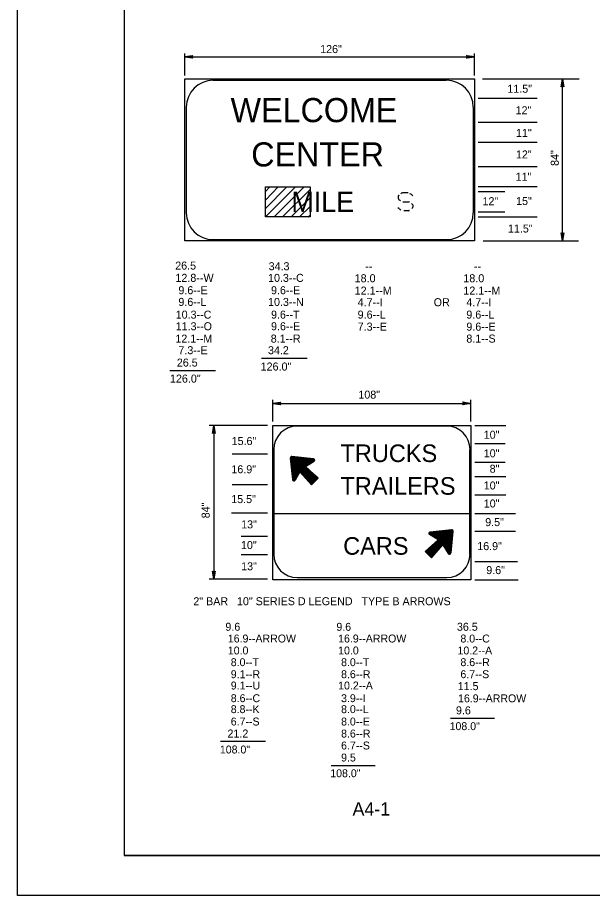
# Model space of a CAD drawing. Extents: x 2189973 to 2192941, y 2147557 to 2151454.
# Drawn here: x 2189973 to 2190680, y 2147557 to 2148636 of the extents above; entities that cross this region are included whole.
import ezdxf

# ---------------------------------------------------------------- set-up
doc = ezdxf.new("R2010")
doc.units = 0
doc.layers.add('Default', color=7, linetype='Continuous')
doc.layers.add('PLT-BNDY', color=7, linetype='Continuous')

# ---------------------------------------------------------------- blocks, each defined once
blk = doc.blocks.new('RARROW')
at = {"layer": 'Default'}
blk.add_lwpolyline([(-18.156, 2.28), (-17.479, 0.966), (0, 0), (-18.156, 2.28), (-19.086, 3.077), (0, 0), (-17.465, -0.864), (-18.103, -2.164), (0, 0), (-19.086, -3.033), (-18.103, -2.164)], dxfattribs=at)

msp = doc.modelspace()

# ---------------------------------------------------------------- linework, layer by layer
at = {"layer": 'Default'}
for p, q in [((2190104.5, 2149456.4), (2190104.5, 2147606)), ((2190179.1, 2148565.2), (2190179.1, 2148592.3)), ((2190535.5, 2148565.2), (2190535.5, 2148592.3)), ((2190179.1, 2148588.2), (2190535.5, 2148588.2)), ((2190179.1, 2148561.1), (2190535.5, 2148561.1)), ((2190179.1, 2148361.8), (2190179.1, 2148561.1)), ((2190500.6, 2148559.1), (2190213.6, 2148559.1)), ((2190535.5, 2148561.1), (2190535.5, 2148361.8)), ((2190545.3, 2148561.1), (2190664, 2148561.1)), ((2190643.6, 2148361.8), (2190643.6, 2148561.1)), ((2190540, 2148537.3), (2190612.5, 2148537.3)), ((2190180.8, 2148525.9), (2190180.8, 2148396.7)), ((2190533.9, 2148396.7), (2190533.9, 2148525.9)), ((2190540, 2148507.8), (2190612.5, 2148507.8)), ((2190540, 2148483.2), (2190612.5, 2148483.2)), ((2190540, 2148453.3), (2190612.5, 2148453.3)), ((2190540, 2148428.7), (2190612.5, 2148428.7)), ((2190540, 2148422.5), (2190572.8, 2148422.5)), ((2190540, 2148397.5), (2190572.8, 2148397.5)), ((2190540, 2148391.3), (2190612.5, 2148391.3)), ((2190213.6, 2148363.5), (2190500.6, 2148363.5)), ((2190535.5, 2148361.8), (2190179.1, 2148361.8)), ((2190545.8, 2148361.8), (2190663.1, 2148361.8)), ((2190273.2, 2148217.5), (2190329.3, 2148217.5)), ((2190160.6, 2148202.3), (2190216.9, 2148202.3)), ((2190287.2, 2148139.8), (2190287.2, 2148166.5)), ((2190287.2, 2148162), (2190530.8, 2148162)), ((2190530.8, 2148139.8), (2190530.8, 2148166.5)), ((2190280.7, 2148134.9), (2190208.9, 2148134.9)), ((2190214.7, 2148134.9), (2190214.7, 2147945.8)), ((2190287.2, 2148109.1), (2190287.2, 2148127.1)), ((2190535.8, 2148134.9), (2190573.8, 2148134.9)), ((2190288.5, 2148105), (2190288.5, 2147976.2)), ((2190529.6, 2147976.2), (2190529.6, 2148105)), ((2190535.8, 2148112.8), (2190573.2, 2148112.8)), ((2190280.7, 2148099.6), (2190237.4, 2148099.6)), ((2190308.6, 2148094.7), (2190311.4, 2148068.5)), ((2190309, 2148095.9), (2190309, 2148095.9)), ((2190309, 2148095.9), (2190309, 2148095.9)), ((2190337.3, 2148093.9), (2190310.6, 2148096.8)), ((2190310.6, 2148095.1), (2190310.6, 2148095.1)), ((2190336.5, 2148092.3), (2190336.5, 2148092.3)), ((2190339.3, 2148092.3), (2190339.3, 2148092.3)), ((2190339.3, 2148092.3), (2190339.3, 2148092.3)), ((2190327.4, 2148084.5), (2190338.1, 2148091)), ((2190327.4, 2148084.5), (2190327.4, 2148084.5)), ((2190343, 2148070.1), (2190327.4, 2148084.5)), ((2190535.8, 2148089.8), (2190573.2, 2148089.8)), ((2190320.5, 2148077.9), (2190314.7, 2148067.6)), ((2190320.5, 2148077.9), (2190320.5, 2148077.9)), ((2190320.5, 2148077.9), (2190334.8, 2148061.9)), ((2190324.1, 2148081.2), (2190324.1, 2148081.2)), ((2190535.8, 2148072.2), (2190573.8, 2148072.2)), ((2190280.7, 2148061.9), (2190237.4, 2148061.9)), ((2190313.5, 2148068.5), (2190313.5, 2148068.5)), ((2190313.5, 2148066), (2190313.5, 2148066)), ((2190313.5, 2148066), (2190313.5, 2148066)), ((2190334.8, 2148061.9), (2190343, 2148070.1)), ((2190334.8, 2148061.9), (2190334.8, 2148061.9)), ((2190343, 2148070.1), (2190343, 2148070.1)), ((2190535.8, 2148049.6), (2190573.8, 2148049.6)), ((2190287.2, 2148022.1), (2190287.2, 2148034)), ((2190280.7, 2148027), (2190236.6, 2148027)), ((2190287.2, 2148026.6), (2190529.6, 2148026.6)), ((2190535.8, 2148026.6), (2190585.9, 2148026.6)), ((2190507.1, 2148006.5), (2190480.8, 2148003.7)), ((2190280.7, 2147998.3), (2190248.3, 2147998.3)), ((2190478.8, 2148001.6), (2190478.8, 2148001.6)), ((2190478.8, 2148001.6), (2190478.8, 2148001.6)), ((2190490.7, 2147994.2), (2190480, 2148000.8)), ((2190480.8, 2148001.6), (2190480.8, 2148001.6)), ((2190506.6, 2147978.2), (2190509.1, 2148004.5)), ((2190507.1, 2148004.5), (2190507.1, 2148004.5)), ((2190535.8, 2148004.9), (2190585.9, 2148004.9)), ((2190490.7, 2147994.2), (2190474.7, 2147979.9)), ((2190482.5, 2147972.1), (2190496.4, 2147988.1)), ((2190490.7, 2147994.2), (2190490.7, 2147994.2)), ((2190493.5, 2147991), (2190493.5, 2147991)), ((2190496.4, 2147988.1), (2190496.4, 2147988.1)), ((2190496.4, 2147988.1), (2190503, 2147977.4)), ((2190280.7, 2147975.8), (2190248.3, 2147975.8)), ((2190474.7, 2147979.9), (2190474.7, 2147979.9)), ((2190474.7, 2147979.9), (2190482.5, 2147972.1)), ((2190504.6, 2147978.7), (2190504.6, 2147978.7)), ((2190504.6, 2147976.2), (2190504.6, 2147976.2)), ((2190504.6, 2147976.2), (2190504.6, 2147976.2)), ((2190482.5, 2147972.1), (2190482.5, 2147972.1)), ((2190535.8, 2147967.6), (2190588.2, 2147967.6)), ((2190280.7, 2147945.8), (2190208.9, 2147945.8)), ((2190535.8, 2147945), (2190589, 2147945)), ((2190505.8, 2147774.8), (2190559.8, 2147774.8)), ((2190223, 2147746.5), (2190278.3, 2147746.5)), ((2190358.9, 2147716.6), (2190413.3, 2147716.6)), ((2192683.2, 2147606), (2190104.5, 2147606)), ((2190104.5, 2147606), (2192027, 2147606))]:
    msp.add_line(p, q, dxfattribs=at)
msp.add_lwpolyline([(2190278.4, 2148391.3), (2190278.4, 2148428.3), (2190333.3, 2148428.3), (2190333.3, 2148391.3)], close=True, dxfattribs=at)
for points in [[(2190278.4, 2148391.3), (2190315.3, 2148428.3)], [(2190278.4, 2148401.6), (2190304.6, 2148428.3)], [(2190278.4, 2148411.8), (2190293.9, 2148428.3)], [(2190278.4, 2148422.5), (2190283.7, 2148428.3)], [(2190289, 2148391.3), (2190325.9, 2148428.3)], [(2190299.3, 2148391.3), (2190333.3, 2148425)], [(2190309.9, 2148391.3), (2190333.3, 2148414.7)], [(2190320.2, 2148391.3), (2190333.3, 2148404.1)], [(2190330.9, 2148391.3), (2190333.3, 2148393.4)], [(2190287.2, 2148134.9), (2190530.8, 2148134.9), (2190530.8, 2148118.1), (2190530.8, 2148096.4), (2190530.8, 2148080), (2190530.8, 2148058.2), (2190530.8, 2148041.4), (2190530.8, 2148025.4), (2190530.8, 2147989.3), (2190530.8, 2147945), (2190287.2, 2147945), (2190287.2, 2147995.9), (2190287.2, 2148018), (2190287.2, 2148041.4), (2190287.2, 2148069.7), (2190287.2, 2148105), (2190287.2, 2148134.9)], [(2190500.9, 2148134.1), (2190317.6, 2148134.1)], [(2190309.8, 2148095.1), (2190312.3, 2148068.9), (2190312.3, 2148067.6), (2190313.9, 2148066.8), (2190314.3, 2148067.6), (2190320.5, 2148079.5), (2190321.7, 2148078.7), (2190335.2, 2148063.1), (2190342.6, 2148070.5), (2190326.6, 2148084.1), (2190327, 2148084.9), (2190338.1, 2148091.4), (2190338.9, 2148092.3), (2190338.5, 2148093.1), (2190337.3, 2148093.1), (2190310.6, 2148095.9), (2190309.8, 2148095.9), (2190309.8, 2148095.1), (2190310.2, 2148095.1), (2190313.5, 2148067.6), (2190320.5, 2148080), (2190335.2, 2148064), (2190341.8, 2148070.1), (2190325.8, 2148084.9), (2190338.5, 2148092.3), (2190310.2, 2148095.5), (2190313.9, 2148069.3), (2190320.5, 2148080.8), (2190335.2, 2148064.4), (2190341.4, 2148070.1), (2190325, 2148084.9), (2190337.3, 2148092.3), (2190310.6, 2148095.1), (2190313.9, 2148070.1), (2190320.5, 2148081.2), (2190335.6, 2148065.2), (2190340.6, 2148070.1), (2190324.6, 2148084.9), (2190335.6, 2148092.3), (2190311, 2148094.7), (2190313.9, 2148071.8), (2190320.5, 2148081.2), (2190335.6, 2148066), (2190339.7, 2148070.1), (2190324.1, 2148085.3), (2190334.8, 2148091.8), (2190311.4, 2148093.9), (2190314.3, 2148073), (2190320.5, 2148081.6), (2190335.6, 2148066.8), (2190339.3, 2148070.5), (2190323.7, 2148085.3), (2190333.6, 2148091), (2190312.3, 2148093.1), (2190315.1, 2148074.2), (2190320.5, 2148082), (2190335.6, 2148067.6), (2190338.9, 2148070.5), (2190323.7, 2148085.3), (2190331.9, 2148090.2), (2190312.7, 2148093.1), (2190315.5, 2148076.3), (2190320.5, 2148083.2), (2190335.6, 2148068.5), (2190338.1, 2148070.5), (2190323.3, 2148085.3), (2190331.1, 2148089.8), (2190313.5, 2148092.3), (2190315.9, 2148077.5), (2190320, 2148084.1), (2190335.6, 2148069.3), (2190337.3, 2148070.5), (2190322.5, 2148085.3), (2190329.5, 2148089.4), (2190313.9, 2148091.8), (2190315.9, 2148078.3), (2190320, 2148084.5), (2190335.6, 2148069.7), (2190336.5, 2148070.5), (2190322.1, 2148085.3), (2190327.8, 2148089.4), (2190314.7, 2148091.4), (2190315.9, 2148080), (2190320, 2148085.3), (2190335.6, 2148070.1), (2190335.6, 2148070.1), (2190321.3, 2148085.3), (2190326.6, 2148089), (2190315.5, 2148090.2), (2190316.4, 2148081.2), (2190320, 2148085.3), (2190335.6, 2148070.1), (2190320.5, 2148085.7), (2190325.4, 2148089), (2190315.9, 2148089.8), (2190316.8, 2148082), (2190320, 2148085.7), (2190327.4, 2148078.7), (2190320, 2148086.1), (2190324.6, 2148088.6), (2190316.4, 2148089.4)], [(2190316.4, 2148089.4), (2190317.6, 2148084.1), (2190323.7, 2148088.2), (2190316.8, 2148089), (2190318, 2148084.9), (2190322.9, 2148088.2), (2190317.6, 2148088.2), (2190318, 2148085.3), (2190321.3, 2148088.2), (2190318, 2148088.2), (2190318, 2148086.1), (2190320, 2148087.7), (2190318, 2148087.7), (2190318.4, 2148087.7), (2190319.2, 2148087.7)], [(2190507.1, 2148005.7), (2190481.2, 2148002.9), (2190480, 2148002.9), (2190479.6, 2148001.6), (2190480, 2148001.2), (2190491.5, 2147994.2), (2190491.5, 2147994.2), (2190475.5, 2147979.9), (2190482.9, 2147972.5), (2190496, 2147988.1), (2190496.8, 2147988.1), (2190503.4, 2147977.4), (2190504.6, 2147976.6), (2190505, 2147977.4), (2190505.4, 2147978.2), (2190508.3, 2148004.9), (2190508.3, 2148005.3), (2190507.5, 2148006.1), (2190507.1, 2148004.9), (2190480, 2148002), (2190492.3, 2147994.2), (2190475.9, 2147979.9), (2190482.5, 2147972.5), (2190496.8, 2147989.7), (2190504.6, 2147977.4), (2190507.9, 2148005.3), (2190481.2, 2148001.6), (2190492.7, 2147994.2), (2190476.7, 2147979.9), (2190482.5, 2147974.1), (2190496.8, 2147990.1), (2190504.2, 2147978.7), (2190507.1, 2148004.5), (2190482.5, 2148001.6), (2190493.1, 2147994.2), (2190477.5, 2147979.9), (2190482.5, 2147975), (2190496.8, 2147990.6), (2190504.2, 2147979.5), (2190507.1, 2148003.7), (2190483.7, 2148001.2), (2190493.5, 2147994.7), (2190478.8, 2147979.9), (2190482.5, 2147975.8), (2190496.8, 2147991), (2190503.8, 2147980.3), (2190506.6, 2148003.7), (2190485.3, 2148001.2), (2190494.8, 2147994.7), (2190479.6, 2147979.9), (2190482.9, 2147976.2), (2190496.8, 2147991.8), (2190503, 2147981.9), (2190505.4, 2148002.9), (2190487.4, 2148000.8), (2190495.2, 2147994.7), (2190480, 2147979.9), (2190482.9, 2147976.6), (2190496.8, 2147991.8), (2190503, 2147983.2), (2190505, 2148002.4), (2190488.6, 2148000), (2190495.6, 2147994.7), (2190480.8, 2147979.9), (2190482.9, 2147977.8), (2190497.2, 2147992.2), (2190503, 2147984.4), (2190504.6, 2148002), (2190489.4, 2147999.6), (2190496, 2147994.7), (2190481.2, 2147979.9), (2190482.9, 2147978.7), (2190497.2, 2147993), (2190502.5, 2147986), (2190503.8, 2148001.6), (2190491.1, 2147999.6), (2190496.4, 2147994.7), (2190481.6, 2147979.9), (2190482.9, 2147978.7), (2190497.2, 2147993.8), (2190501.7, 2147987.3), (2190503.4, 2148001.2), (2190492.3, 2147999.6), (2190496.8, 2147994.7), (2190482.5, 2147979.9), (2190482.5, 2147979.1), (2190497.6, 2147994.2), (2190501.3, 2147988.9), (2190503, 2148000), (2190493.5, 2147999.2), (2190497.2, 2147995.1), (2190482.5, 2147979.5), (2190498.4, 2147994.7), (2190501.3, 2147990.1), (2190503, 2147999.6), (2190495.2, 2147998.8), (2190498.4, 2147995.1), (2190491.5, 2147988.1), (2190498.9, 2147995.1), (2190500.9, 2147990.6), (2190502.5, 2147999.2)], [(2190502.5, 2147999.2), (2190496, 2147998.3), (2190500.5, 2147991.8), (2190501.3, 2147998.8), (2190496.8, 2147997.9), (2190500.5, 2147992.2), (2190500.5, 2147997.9), (2190497.6, 2147997.5), (2190500.1, 2147994.2), (2190500.1, 2147997.5), (2190498.9, 2147997.1), (2190499.7, 2147994.7), (2190499.7, 2147997.1), (2190499.7, 2147997.1), (2190499.7, 2147995.9)], [(2190317.6, 2147947.9), (2190500.9, 2147947.9)]]:
    msp.add_lwpolyline(points, dxfattribs=at)
for centre, radius, start, end in [((2190213.8, 2148526.3), 33, 90, 180), ((2190500.8, 2148526.3), 33, 0, 90), ((2190213.8, 2148396.4), 33, 180, 270), ((2190500.8, 2148396.4), 33, 270, 0), ((2190317.1, 2148105.3), 28.7, 90, 180), ((2190501.1, 2148105.3), 28.7, 0, 90), ((2190310.4, 2148094.9), 1.69, 84.0498, 185.9502), ((2190336.9, 2148092.2), 1.69, 301.5539, 84.0498), ((2190313.2, 2148068.4), 1.69, 185.9502, 328.4461), ((2190507.3, 2148004.8), 1.69, 354.0498, 95.9502), ((2190480.7, 2148002), 1.69, 95.9502, 238.4461), ((2190317.1, 2147976.5), 28.7, 180, 270), ((2190501.1, 2147976.5), 28.7, 270, 0), ((2190504.5, 2147978.2), 1.69, 211.5539, 354.0498)]:
    msp.add_arc(centre, radius, start, end, dxfattribs=at)
for points in [[(2190442.4, 2148418), (2190442, 2148417.6), (2190441.6, 2148417.2), (2190441.6, 2148414.3), (2190442, 2148412.7), (2190443.6, 2148411.8), (2190444.5, 2148411)], [(2190453.9, 2148420.9), (2190453.1, 2148420.9), (2190451.8, 2148420.9), (2190447.7, 2148420.9), (2190446.9, 2148420.9), (2190444.9, 2148419.6)], [(2190459.6, 2148417.2), (2190458, 2148418.8), (2190455.9, 2148419.6)], [(2190447.3, 2148409.8), (2190448.6, 2148409.8), (2190450.2, 2148409.8), (2190452.2, 2148409.8), (2190453.9, 2148409.8), (2190455.1, 2148409.8), (2190455.5, 2148409.4)], [(2190458, 2148407.7), (2190458.8, 2148406.9), (2190459.2, 2148406.1), (2190459.6, 2148405.7), (2190459.6, 2148404.1), (2190459.2, 2148402.8), (2190458.4, 2148401.2)], [(2190444.9, 2148399.5), (2190444.5, 2148400), (2190443.2, 2148400.8), (2190441.2, 2148402.4)], [(2190454.7, 2148398.7), (2190455.1, 2148399.1), (2190453.9, 2148398.7), (2190451.8, 2148398.7), (2190449.8, 2148398.7), (2190448.6, 2148398.7)]]:
    msp.add_spline(points, degree=3, dxfattribs=at)
at = {"layer": 'PLT-BNDY'}
msp.add_lwpolyline([(2189973.2, 2149505.6), (2192732.4, 2149505.6), (2192732.4, 2147556.8), (2189973.2, 2147556.8)], close=True, dxfattribs=at)

# ---------------------------------------------------------------- block references
at = {"layer": 'Default', "xscale": 0.515679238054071, "yscale": 0.5369477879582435}
for p, rotation in [((2190179.1, 2148588.2), 180), ((2190643.6, 2148561.1), 89.99999999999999), ((2190643.6, 2148361.8), -90.00000000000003), ((2190287.2, 2148162), 180), ((2190214.7, 2148134.9), 89.99999999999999), ((2190214.7, 2147945.8), -90.00000000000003)]:
    msp.add_blockref('RARROW', p, dxfattribs=dict(at, rotation=rotation))
for p in [(2190535.5, 2148588.2), (2190530.8, 2148162)]:
    msp.add_blockref('RARROW', p, dxfattribs=at)

# ---------------------------------------------------------------- texts
at = {"layer": 'Default'}
for s, height, p in [('126"', 9.84, (2190345.5, 2148592.8)), ('11.5"', 9.84, (2190575.8, 2148544)), ('12"', 9.84, (2190585.9, 2148517.5)), ('11"', 9.84, (2190586.4, 2148489.7)), ('12"', 9.84, (2190586.3, 2148463.2)), ('11"', 9.84, (2190585.9, 2148435.8)), ('12"', 9.84, (2190545.2, 2148405.7)), ('15"', 9.84, (2190586.5, 2148405.9)), ('11.5"', 9.84, (2190576.5, 2148372.1)), ('26.5', 9.84, (2190167.2, 2148326.5)), ('34.3', 9.84, (2190282.1, 2148325.7)), ('12.8--W', 9.89, (2190167.4, 2148311.4)), ('10.3--C', 9.84, (2190281.4, 2148311.4)), ('18.0   ', 9.89, (2190387.9, 2148310.9)), ('18.0   ', 9.89, (2190521.6, 2148310.9)), (' 9.6--E', 9.89, (2190167.4, 2148296.2)), (' 9.6--E', 9.84, (2190281.4, 2148296.2)), ('12.1--M', 9.89, (2190387.9, 2148295.7)), ('12.1--M', 9.89, (2190521.6, 2148295.7)), (' 9.6--L', 9.89, (2190167.4, 2148281.8)), ('10.3--N', 9.84, (2190281.4, 2148281.8)), (' 4.7--I', 9.89, (2190387.9, 2148281.4)), ('OR', 9.89, (2190485.1, 2148281.4)), (' 4.7--I', 9.89, (2190521.6, 2148281.4)), ('10.3--C', 9.84, (2190167.8, 2148266.2)), (' 9.6--T', 9.84, (2190281.4, 2148266.2)), (' 9.6--L', 9.89, (2190387.9, 2148266.2)), (' 9.6--L', 9.89, (2190521.6, 2148266.2)), ('11.3--O', 9.84, (2190167.8, 2148251.9)), (' 9.6--E', 9.84, (2190281.4, 2148251.9)), (' 7.3--E', 9.89, (2190387.9, 2148251.4)), (' 9.6--E', 9.89, (2190521.6, 2148251.4)), ('12.1--M', 9.84, (2190167.4, 2148236.7)), (' 8.1--R', 9.89, (2190281, 2148236.7)), (' 8.1--S', 9.89, (2190521.6, 2148236.7)), (' 7.3--E', 9.89, (2190167.4, 2148222.4)), ('34.2', 9.84, (2190281.3, 2148222.4)), ('26.5  ', 9.84, (2190169.2, 2148207.2)), ('126.0"     ', 9.894, (2190272.2, 2148202.3)), ('126.0"', 9.89, (2190160.7, 2148187.5)), ('108"', 9.84, (2190392.5, 2148167.8)), ('10"', 9.84, (2190546.7, 2148118.5)), ('15.6"', 9.84, (2190236.6, 2148110.7)), ('10"', 9.84, (2190546.7, 2148095.6)), ('16.9"', 9.84, (2190236.3, 2148076)), ('8"', 9.84, (2190554, 2148076.7)), ('10"', 9.84, (2190546.7, 2148056.1)), ('15.5"', 9.84, (2190236.1, 2148039.3)), ('10"', 9.84, (2190546.7, 2148033.9)), ('13"', 9.84, (2190248.3, 2148008.2)), ('9.5"', 9.84, (2190548.5, 2148011)), ('10"', 9.84, (2190248.1, 2147982.8)), ('16.9"', 9.84, (2190538.7, 2147981.5)), ('13"', 9.84, (2190248.3, 2147956.7)), ('9.6"', 9.84, (2190549.8, 2147952)), ('2" BAR   10" SERIES D LEGEND   TYPE B ARROWS', 9.842, (2190189.5, 2147913.7)), ('  9.6        ', 9.842, (2190221.6, 2147882.3)), ('  9.6        ', 9.732, (2190358.2, 2147882.3)), ('36.5     ', 9.84, (2190513.7, 2147882.3)), ('16.9--ARROW', 9.732, (2190231.9, 2147867.9)), ('16.9--ARROW', 9.732, (2190367.6, 2147867.9)), (' 8.0--C    ', 9.732, (2190514.4, 2147867.9)), ('10.0       ', 9.732, (2190231.9, 2147853.2)), ('10.0       ', 9.732, (2190367.6, 2147853.2)), ('10.2--A    ', 9.732, (2190514.4, 2147853.2)), (' 8.0--T    ', 9.732, (2190231.9, 2147838.8)), (' 8.0--T    ', 9.732, (2190367.6, 2147838.8)), (' 8.6--R    ', 9.732, (2190514.4, 2147838.8)), (' 9.1--R    ', 9.732, (2190231.9, 2147824)), (' 8.6--R    ', 9.732, (2190367.6, 2147824)), (' 6.7--S    ', 9.732, (2190514.4, 2147824)), (' 9.1--U    ', 9.732, (2190231.9, 2147810.1)), ('10.2--A    ', 9.732, (2190367.6, 2147810.1)), ('11.5       ', 9.842, (2190514.7, 2147809.3)), (' 8.6--C    ', 9.732, (2190231.9, 2147794.5)), (' 3.9--I    ', 9.732, (2190367.6, 2147794.5)), ('16.9--ARROW', 9.732, (2190515.1, 2147794.3)), (' 8.8--K    ', 9.732, (2190231.9, 2147781)), (' 8.0--L    ', 9.732, (2190367.6, 2147781)), ('  9.6        ', 9.842, (2190505.2, 2147779.5)), (' 6.7--S    ', 9.732, (2190231.9, 2147765.8)), (' 8.0--E    ', 9.732, (2190367.6, 2147765.8)), ('108.0"       ', 9.732, (2190504.7, 2147760.1)), ('21.2       ', 9.842, (2190231.5, 2147751)), (' 8.6--R    ', 9.732, (2190367.6, 2147751)), ('108.0"       ', 9.732, (2190222.1, 2147731.4)), (' 6.7--S    ', 9.732, (2190367.6, 2147736.3)), (' 9.5       ', 9.732, (2190367.6, 2147721.5)), ('108.0"        ', 9.732, (2190357.9, 2147702.2)), ('A4-1', 16.4, (2190385.3, 2147655))]:
    msp.add_text(s, height=height, dxfattribs=at).set_placement(p)
for s, height, rotation, p in [('WELCOME', 29.69, 360, (2190235.3, 2148507.8)), ('CENTER', 29.69, 360, (2190260.7, 2148453.3)), ('84"', 9.84, 90, (2190639, 2148454)), ('   MILE', 24.74, 360, (2190282.5, 2148397.5)), ('     -- ', 9.89, 360, (2190382.5, 2148325.7)), ('     -- ', 9.89, 360, (2190516.2, 2148325.7)), ('TRUCKS', 21.64, 360, (2190370.5, 2148089.8)), ('TRAILERS', 21.64, 360, (2190370.5, 2148049.6)), ('84"', 9.84, 90, (2190209.5, 2148020.6)), ('CARS', 21.64, 360, (2190373.8, 2147975.8))]:
    msp.add_text(s, height=height, rotation=rotation, dxfattribs=at).set_placement(p)

doc.saveas('drawing.dxf')
